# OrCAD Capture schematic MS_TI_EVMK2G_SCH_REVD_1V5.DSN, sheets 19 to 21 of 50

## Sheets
19 18. NAND FLASH & MICRO SD CARD: size C; title: NAND FLASH & SD CARD
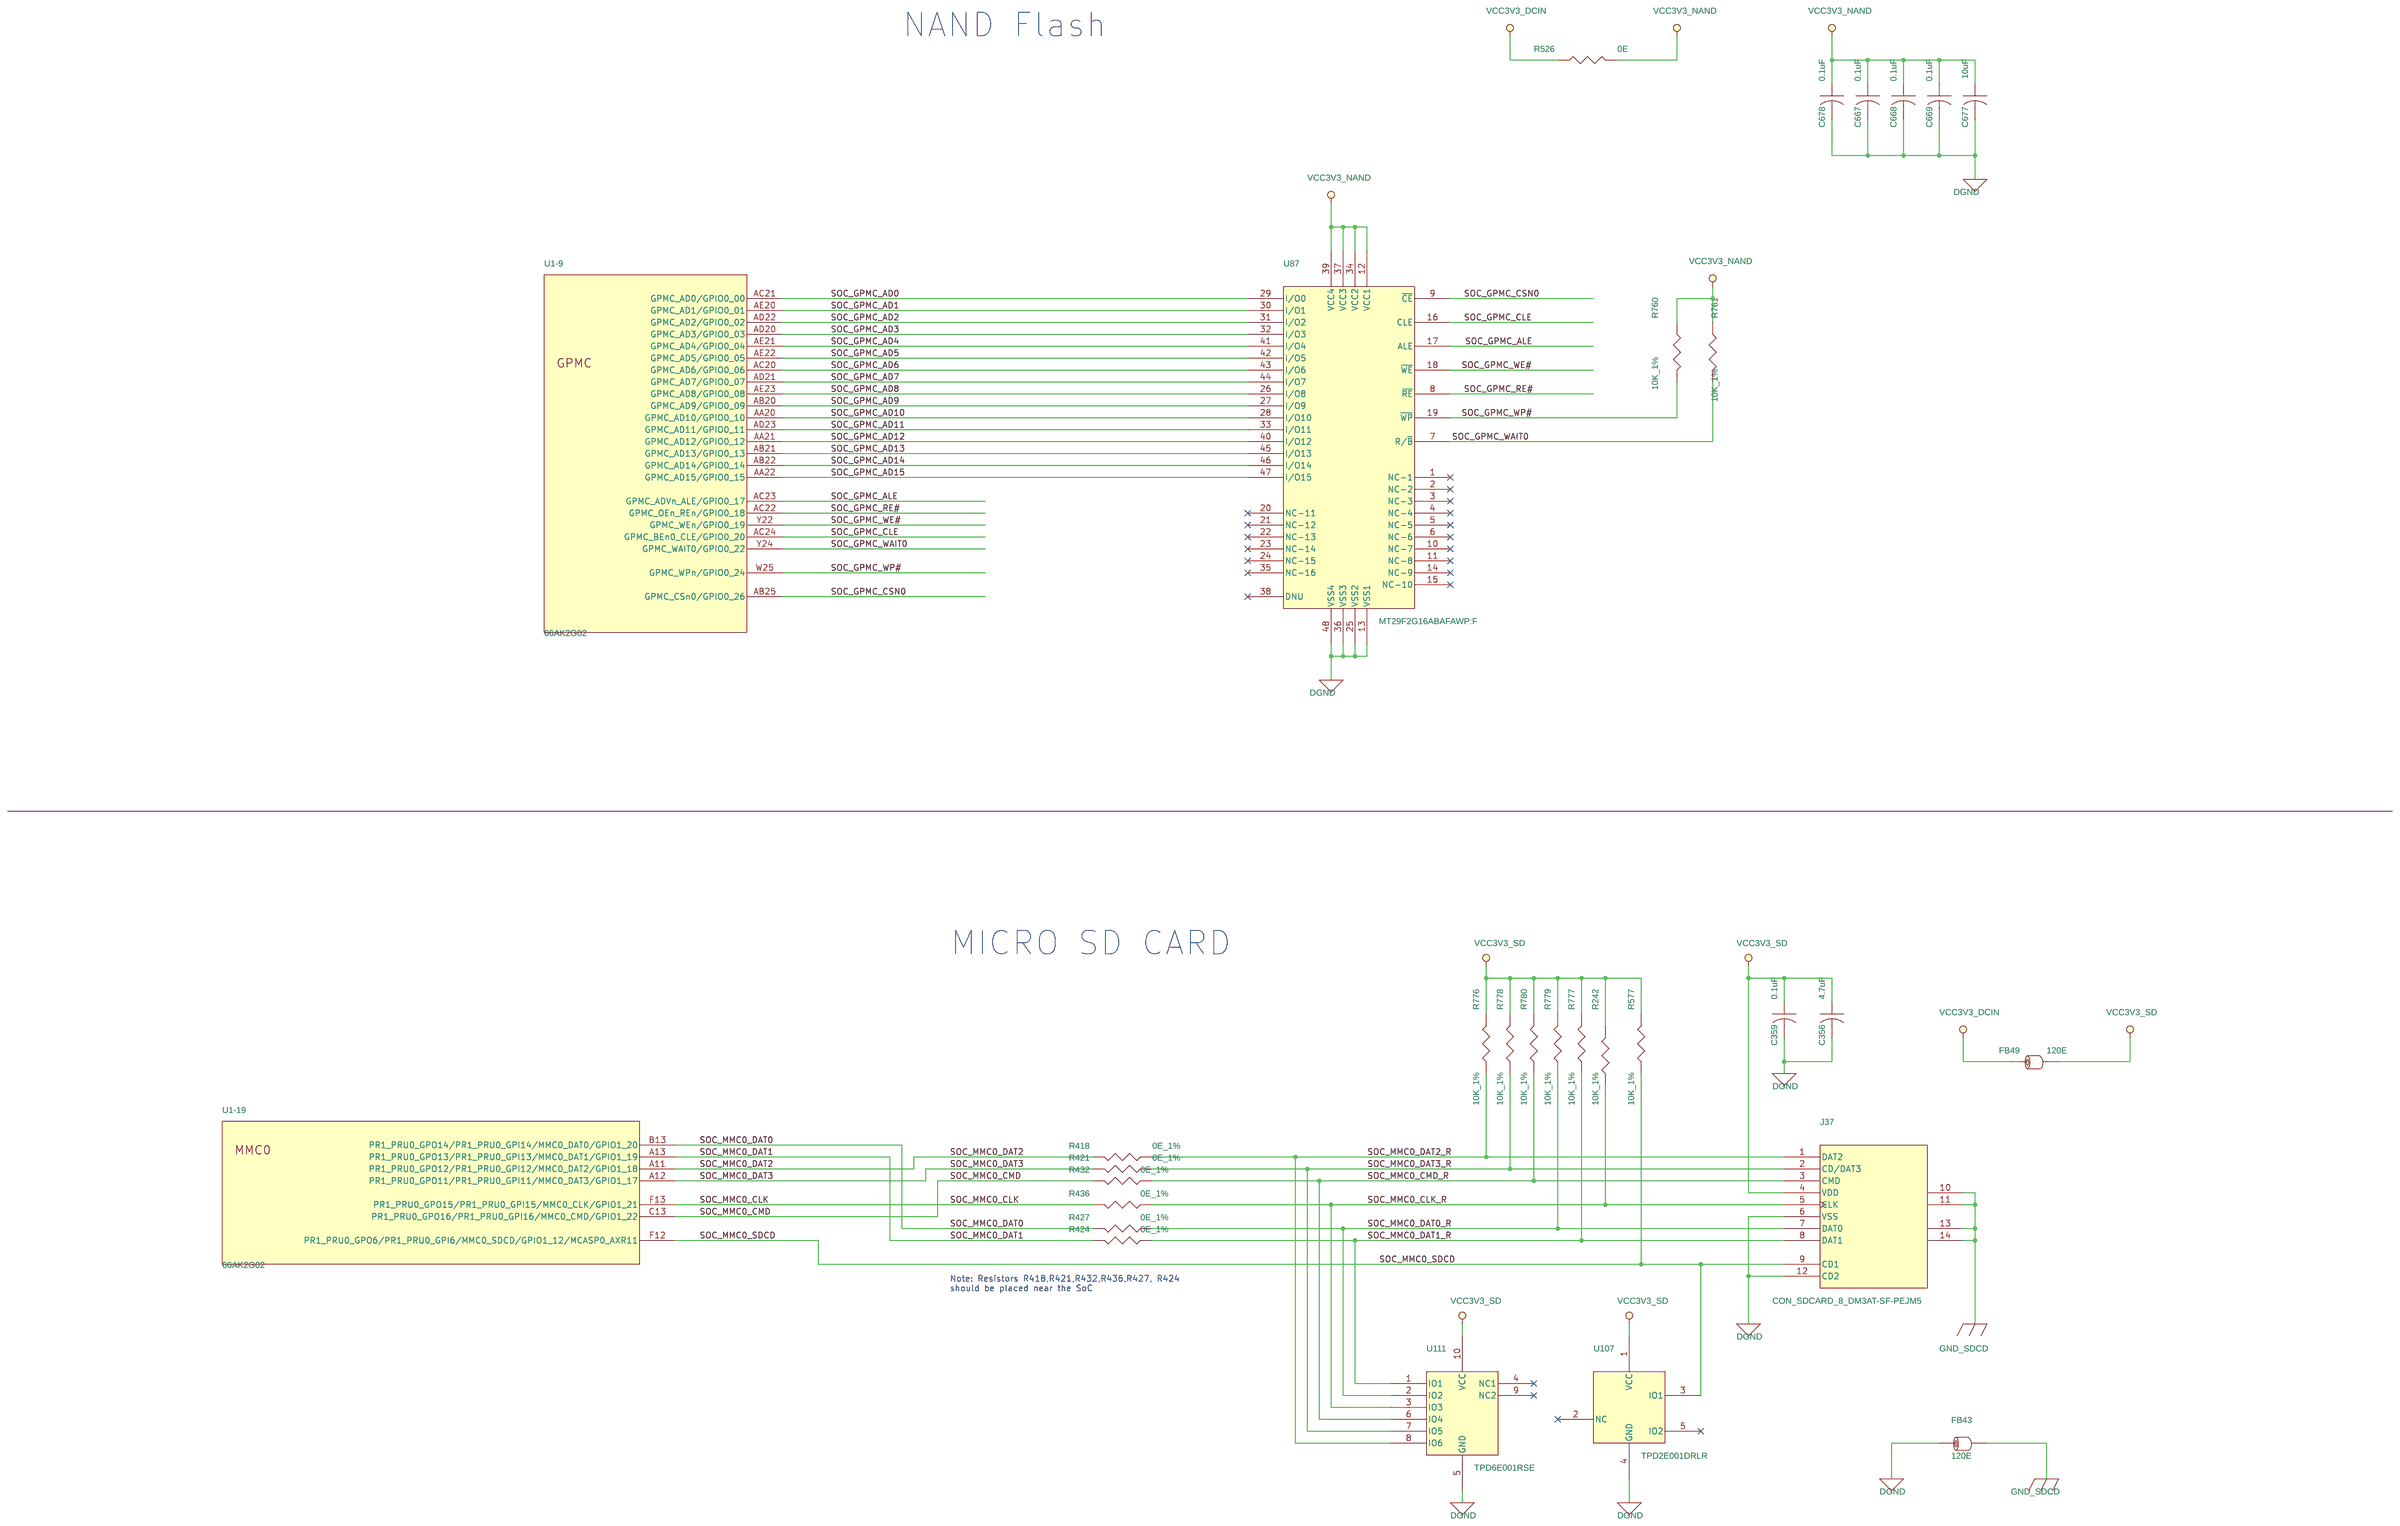
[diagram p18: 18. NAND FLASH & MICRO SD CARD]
20 19. DSS BUFFER: size C; title: DSS BUFFER SECTION
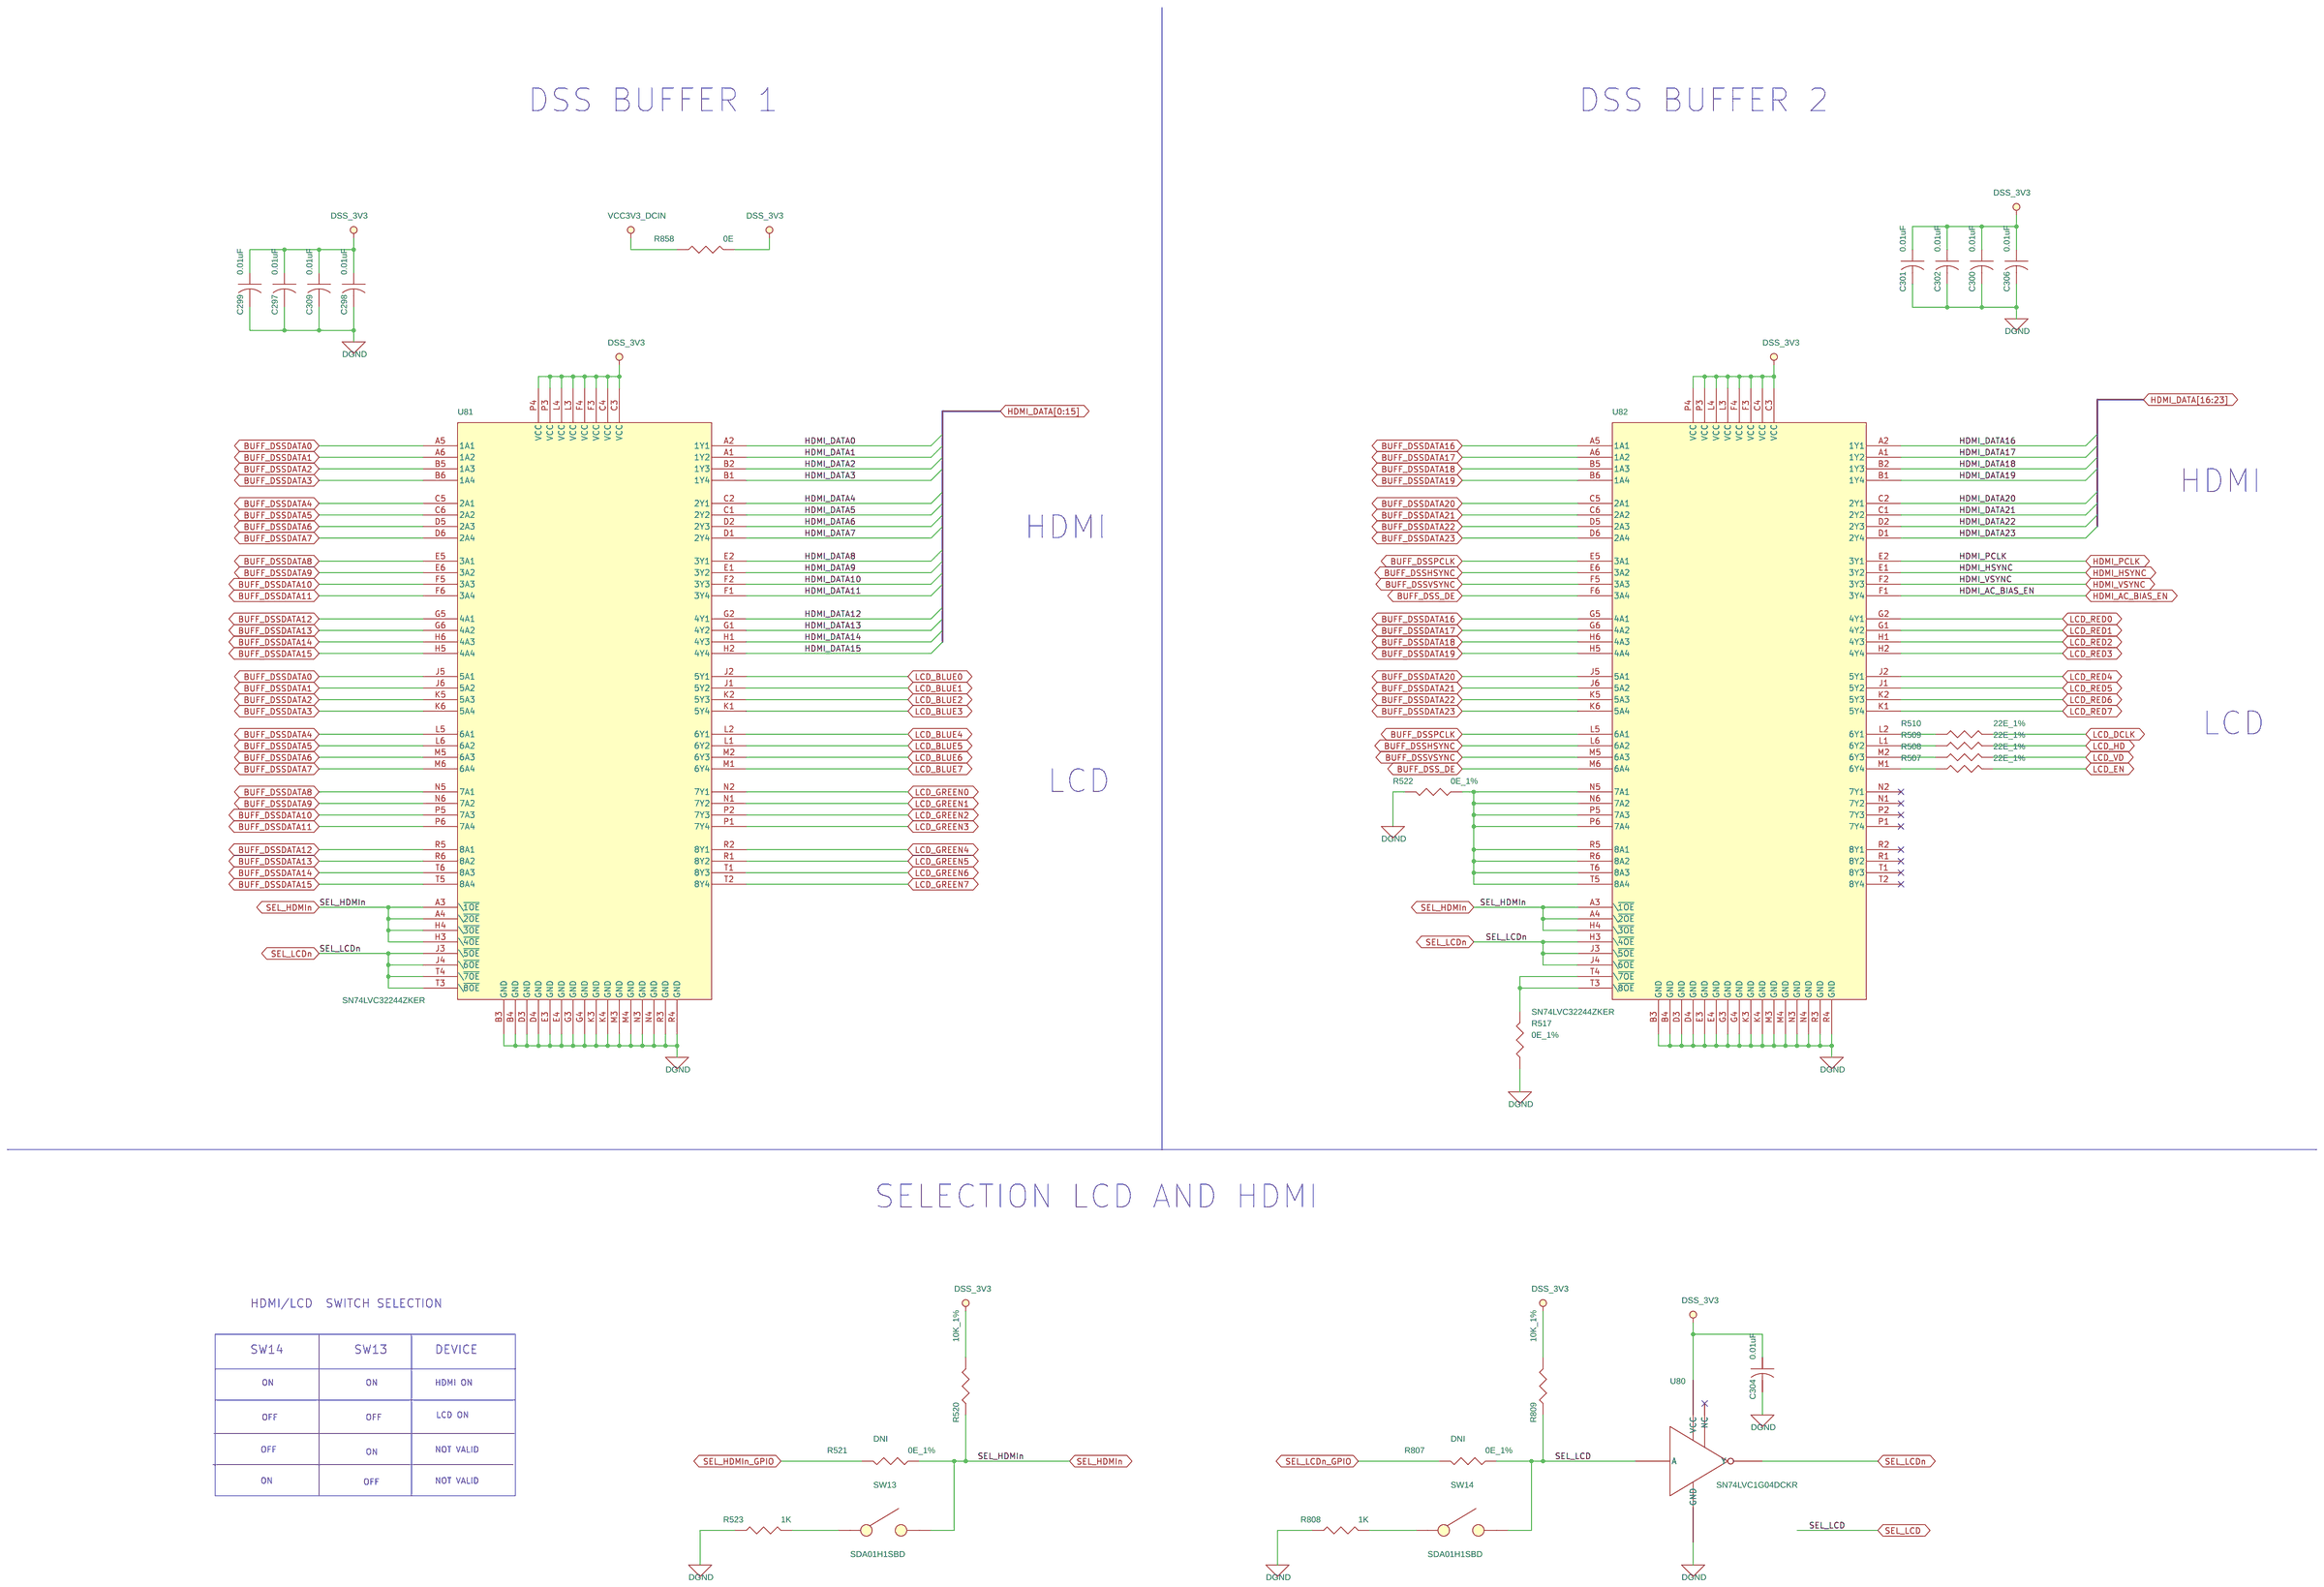
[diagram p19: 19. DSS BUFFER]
21 20. LCD & TOUCH CONNECTOR: size C; title: LCD & TOUCH SCREEN
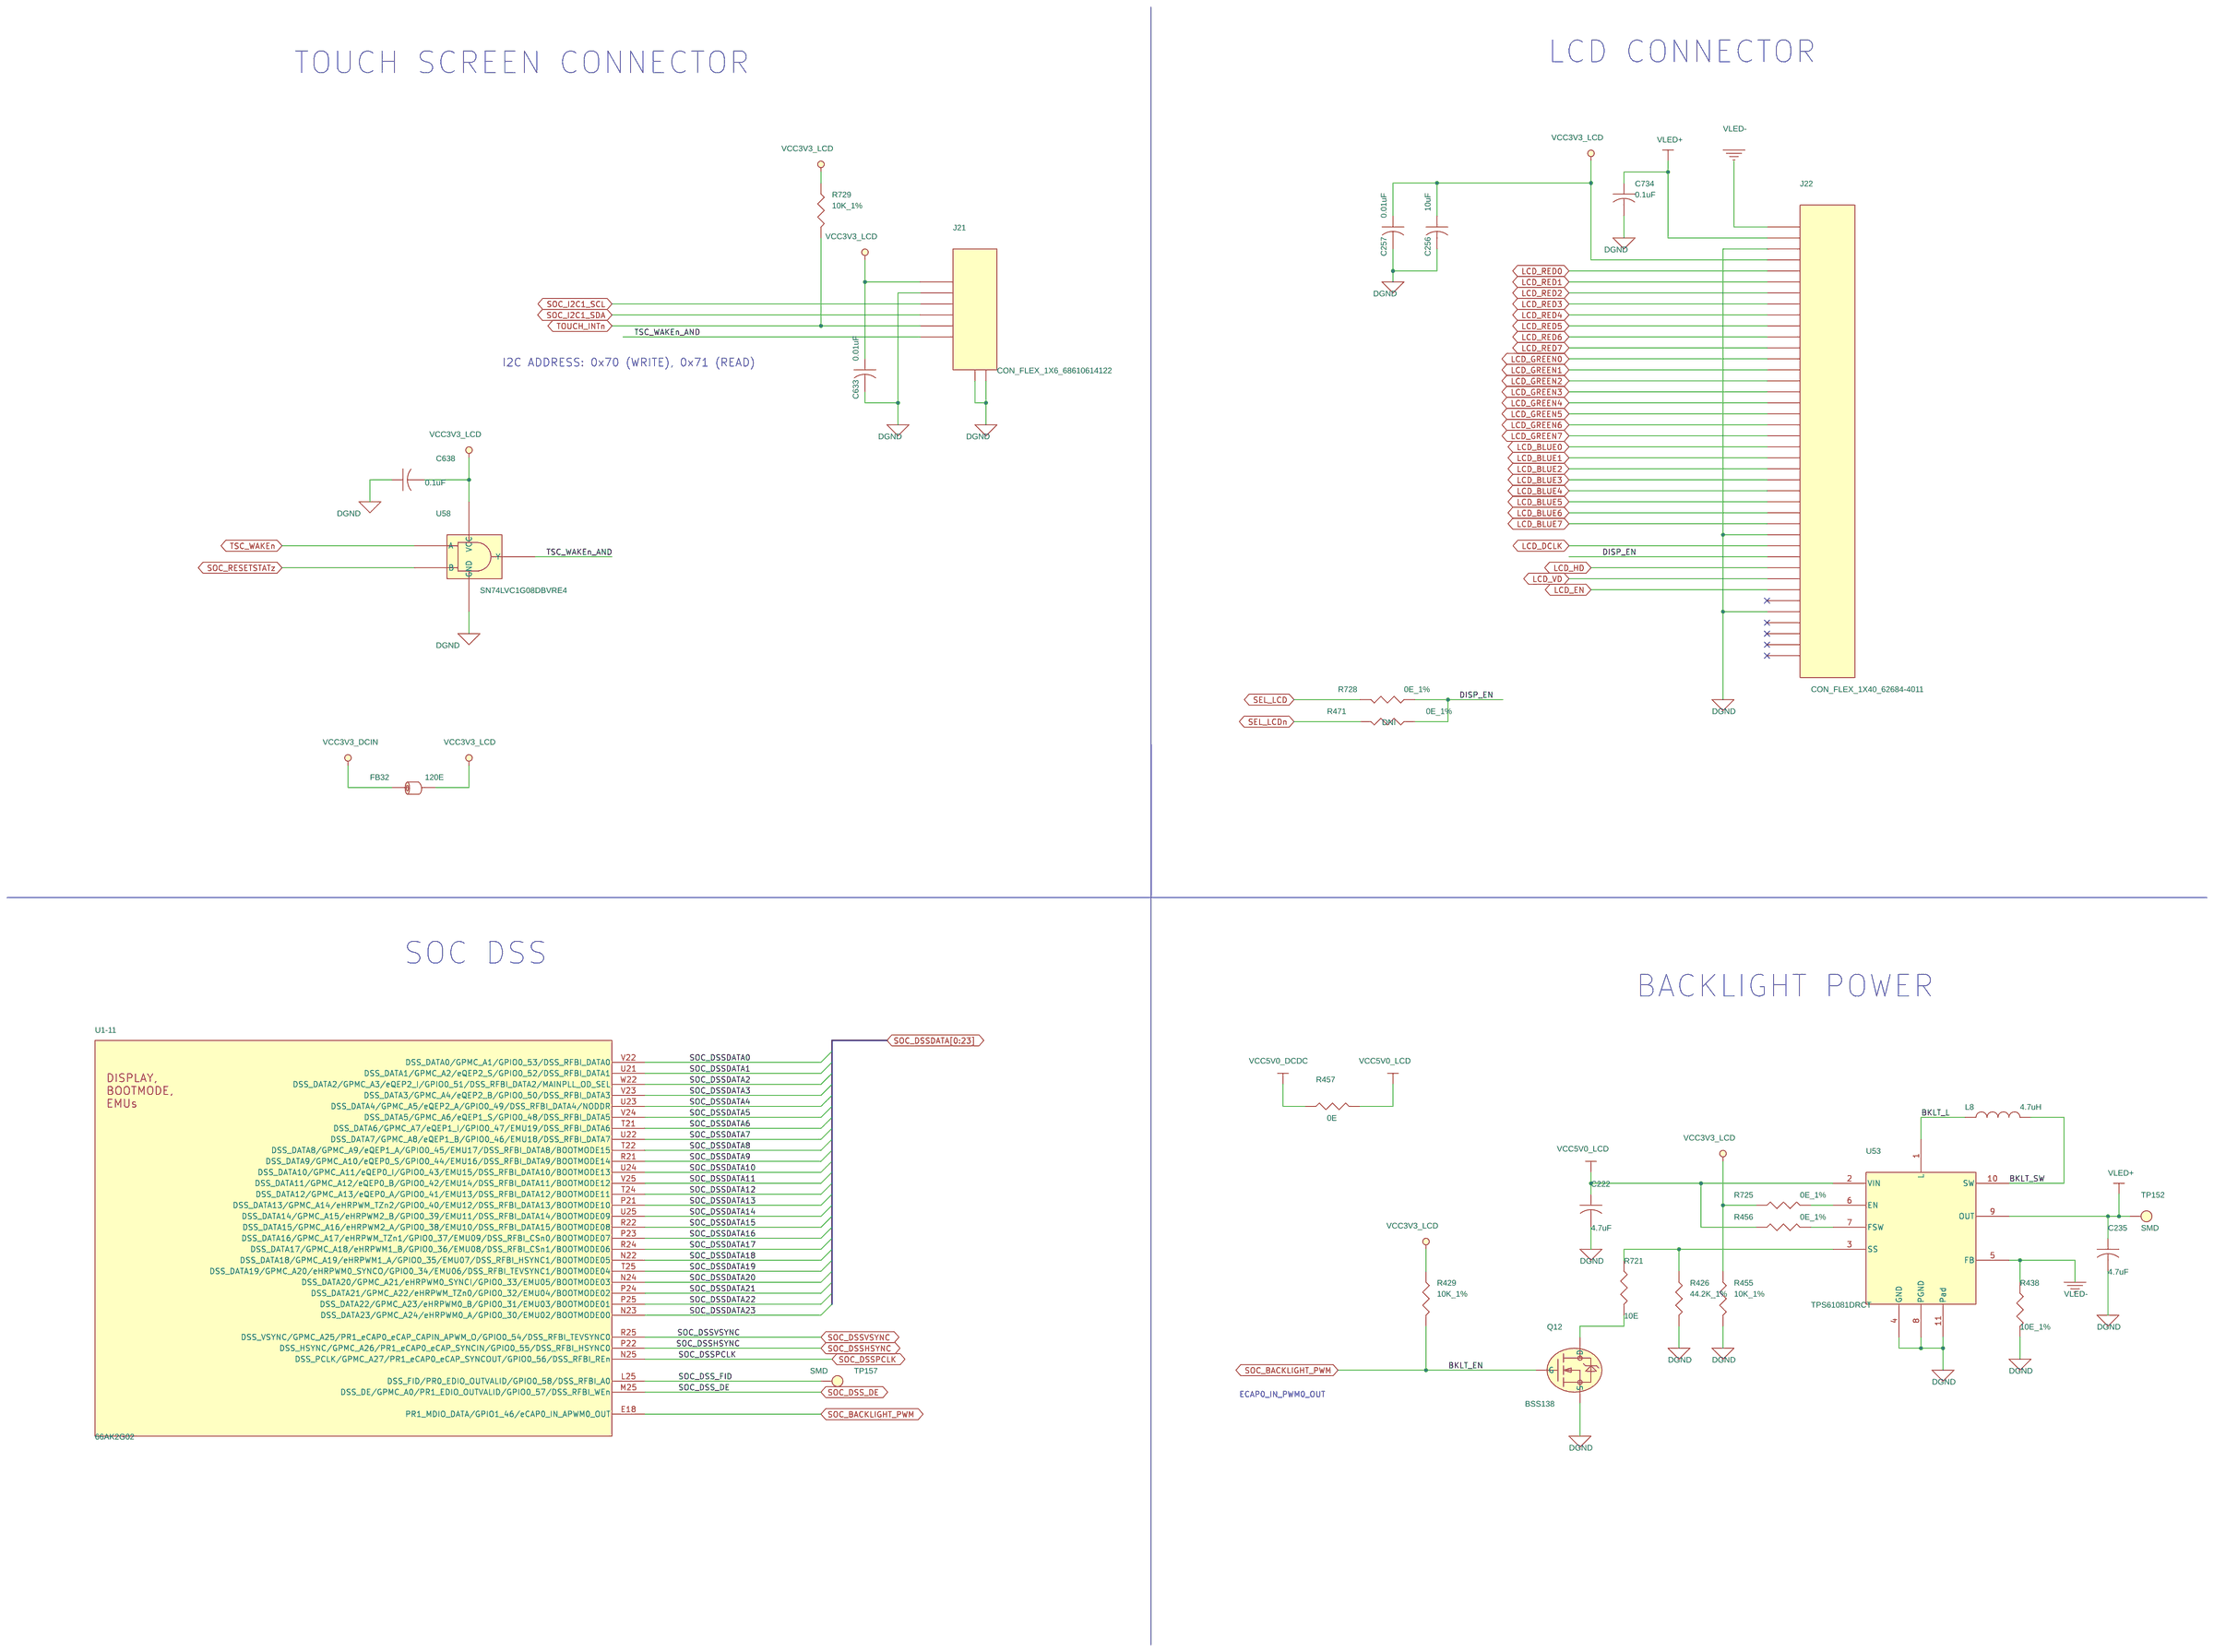
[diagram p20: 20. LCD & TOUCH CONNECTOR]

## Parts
sheet 18. NAND FLASH & MICRO SD CARD
C356  4.7uF  [CAP0603]
C359  0.1uF  [CAP0402]
C667  0.1uF  [CAP0402]
C668  0.1uF  [CAP0402]
C669  0.1uF  [CAP0402]
C677  10uF  [CAP0805]
C678  0.1uF  [CAP0402]
FB43  120E  [IND0402]
FB49  120E  [IND0402]
J37  CON_SDCARD_8_DM3AT-SF-PEJM5  [CON_SD_8_DM3AT-SF-PEJM_S_R_S]
R242  10K_1%  [RES0402]
R418  0E_1%  [RES0402]
R421  0E_1%  [RES0402]
R424  0E_1%  [RES0402]
R427  0E_1%  [RES0402]
R432  0E_1%  [RES0402]
R436  0E_1%  [RES0402]
R526  0E  [RES0402]
R577  10K_1%  [RES0402]
R760  10K_1%  [RES0402]
R761  10K_1%  [RES0402]
R776  10K_1%  [RES0402]
R777  10K_1%  [RES0402]
R778  10K_1%  [RES0402]
R779  10K_1%  [RES0402]
R780  10K_1%  [RES0402]
U87  MT29F2G16ABAFAWP:F  [TSOP48_19-68_730X480]
U107  TPD2E001DRLR  [SOT533-5]
U111  TPD6E001RSE  [UQFN10_19-68_80X60]
sheet 19. DSS BUFFER
C297  0.01uF  [CAP0402]
C298  0.01uF  [CAP0402]
C299  0.01uF  [CAP0402]
C300  0.01uF  [CAP0402]
C301  0.01uF  [CAP0402]
C302  0.01uF  [CAP0402]
C304  0.01uF  [CAP0402]
C306  0.01uF  [CAP0402]
C309  0.01uF  [CAP0402]
R507  22E_1%  [RES0402]
R508  22E_1%  [RES0402]
R509  22E_1%  [RES0402]
R510  22E_1%  [RES0402]
R517  0E_1%  [RES0402]
R520  10K_1%  [RES0402]
R521  0E_1%  [RES0402]
R522  0E_1%  [RES0402]
R523  1K  [RES0402]
R807  0E_1%  [RES0402]
R808  1K  [RES0402]
R809  10K_1%  [RES0402]
R858  0E  [RES0402]
SW13  SDA01H1SBD  [SW2_100X324-80_180X300_SMD]
SW14  SDA01H1SBD  [SW2_100X324-80_180X300_SMD]
U80  SN74LVC1G04DCKR  [SC70-5]
U81  SN74LVC32244ZKER  [LFBGA96_31-49_220X540]
U82  SN74LVC32244ZKER  [LFBGA96_31-49_220X540]
sheet 20. LCD & TOUCH CONNECTOR
C222  4.7uF  [CAP0603]
C235  4.7uF  [CAP0805]
C256  10uF  [CAP0805]
C257  0.01uF  [CAP0402]
C633  0.01uF  [CAP0402]
C638  0.1uF  [CAP0402]
C734  0.1uF  [CAP0402]
FB32  120E  [IND0402]
J21  CON_FLEX_1X6_68610614122  [CON_FLEX_6X1_68610_S_R_S]
J22  CON_FLEX_1X40_62684-4011  [CON_FLEX40X1_62684-40_S_R_S]
L8  4.7uH  [IND_VLCF5020T_205X210_SMD]
Q12  BSS138  [TO_SOT23-123]
R426  44.2K_1%  [RES0402]
R429  10K_1%  [RES0402]
R438  10E_1%  [RES0603]
R455  10K_1%  [RES0402]
R456  0E_1%  [RES0402]
R457  0E  [RES0402]
R471  0E_1%  [RES0402]
R721  10E  [RES0402]
R725  0E_1%  [RES0402]
R728  0E_1%  [RES0402]
R729  10K_1%  [RES0402]
TP152  SMD  [TP40_SMD]
TP157  SMD  [TP40_SMD]
U53  TPS61081DRCT  [SON10_19-68_130X130]
U58  SN74LVC1G08DBVRE4  [SOT23-5]
sheet 36. CLOCK DISTRIBUTION 2
U1  66AK2G02_BGA625  [BGASKT625_31-49_1270x1270]  (sections -1,-10,-11,-12,-13,-14,-15,-16,-17,-18,-19,-2,-20,-21,-22,-23,-24,-25,-26,-27,-28,-29,-3,-30,-31,-32,-33,-34,-35,-36,-37,-38,-4,-5,-6,-7,-8,-9)

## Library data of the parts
C222 C356 = CAP: CAP CERAMIC 4.7uF 16V 10% X5R 0603; Chkd/date: VASANTHA/230714; Crtd /date: BAVISH/060511; Custom_Duty: 15%; Customs_HS_Code: 85322990; Distributor_name: DIGIKEY; Distributor_part_number: 587-2786-1-ND; Height: 0.90MM; Mfr_name: TAIYO YUDEN; Mfr_part_number: EMK107ABJ475KA-T; Mistral Part No: 120011050004-R; Package: 0603; Part_type: CAPACITORS\CERAMIC; Project: HMC; RoHS: RoHS; Temperature: -55°C+85°C; Tolerance: 10%; Voltage: 16V; Wattage: NA; Weight: NA; Datasheet: Y:\MIS_DATABASE\DATASHEETS\CAPACITORS\EMK107.PDF
C359 C638 C667-C669 C678 = CAP: CAP CERAMIC 0.1uF 16V 10% X7R 0402; Alternate_mfr_name_A: KEMET; Alternate_mfr_part_number_A: C0402C104K4RACT; Chkd/date: MAZHAR/281108; Crtd /date: MAZHAR/030907; Custom_Duty: 15%; Customs_HS_Code: 85322990; Distributor_name: DIGIKEY; Distributor_name_A: DIGIKEY; Distributor_part_number: 490-3261-1-ND; Distributor_part_number_A: 399-3521-1-ND; Height: 0.55MM; Mfr_name: MURATA; Mfr_part_number: GRM155R71C104KA88D; Mistral Part No: 120009030060-R; Package: 0402; Part_type: CAPACITORS\CERAMIC; Project: SMART VIEW_IP CAMERA; Tolerance: 10%; Voltage: 16V; Datasheet: Y:\MIS_DATABASE\DATASHEETS\CAPACITORS\GRM188SERIES.PDF
C256 C677 = CAP: CAP CERAMIC 10uF 16V 10% X5R 0805; Alternate_mfr_name_A: TAIYO YUDEN; Alternate_mfr_part_number_A: EMK212BJ106KG-T; Chkd/date: RAVI/020511; Crtd /date: BAVISH/290411; Custom_Duty: 15%; Customs_HS_Code: 85322990; Distributor_name: DIGIKEY; Distributor_name_A: DIGIKEY; Distributor_part_number: 478-5165-1-ND; Distributor_part_number_A: 587-1295-1-ND; Height: 1.40MM; Mfr_name: AVX CORPORATION; Mfr_part_number: 0805YD106KAT2A; Mistral Part No: 120011040011-R; Package: 0805; Part_type: CAPACITORS\CERAMIC; Project: AOD_POD-RF; RoHS: RoHS; Temperature: -55°C+85°C; Tolerance: 10%; Voltage: 16V; Wattage: NA; Weight: NA; Datasheet: Y:\MIS_DATABASE\DATASHEETS\CAPACITORS\AVX_CERAMIC.PDF
FB32 FB43 FB49 = INDUCTOR_FERRITE: IND BEAD CHIP 120E 1.2A 0402; Chkd/date: ASHOK/240212; Crtd /date: BAVISH/060711; Custom_Duty: 24%; Customs_HS_Code: 85437099; Distributor_name: DIGIKEY; Distributor_part_number: 445-2981-1-ND; Height: 0.55MM; Mfr_name: TDK CORPORATION; Mfr_part_number: MPZ1005S121C; Mistral Part No: 130011070007-R; Package: 0402; Part_type: INDUCTOR; Project: SVDU; RoHS: RoHS; Temperature: -40°C+85°C; Tolerance: NA; Voltage: NA; Wattage: NA; Weight: 1mg; Datasheet: Y:\MIS_DATABASE\DATASHEETS\DISCRETES\INDUCTORS\MPZ1005.PDF
J37 = CON_SDCARD_8_DM3AT-SF-PEJM_0: CON SD CARD PUSH-PUSH 8POS SMD; Chkd/date: RAGESH/160511; Crtd /date: BAVISH/130511; Custom_Duty: 24%; Customs_HS_Code: 85369090; Distributor_name: DIGIKEY; Distributor_part_number: HR1964CT-ND; Height: 1.68MM; Mfr_name: HIROSE ELECTRIC EUROPE; Mfr_part_number: DM3AT-SF-PEJM5; Mistral Part No: 150011050017-R; Package: SMD; Part_type: CONNECTOR\MEMORY CARD; Project: HMC; RoHS: RoHS; Temperature: -25°C+85°C; Tolerance: NA; Voltage: NA; Wattage: NA; Weight: NA; Datasheet: Y:\MIS_DATABASE\DATASHEETS\CONNECTORS\DM3AT-PEJM.PDF
R242 R429 R455 R520 R577 R729 R760 R761 R776-R780 R809 = RESISTOR: RES 10K 1/16W 1% 0402; Alternate_mfr_name_A: AVX CORPORATION; Alternate_mfr_name_B: PANASONIC-ECG-ECG; Alternate_mfr_name_C: YAGEO AMERICA; Alternate_mfr_name_D: VISHAY; Alternate_mfr_part_number_A: CR05-103F-H; Alternate_mfr_part_number_B: ERJ-2RKF1002X; Alternate_mfr_part_number_C: 9C04021A1002FLHF3; Alternate_mfr_part_number_D: CRCW040210K0FKED; Chkd/date: SHREESHAIL/310506; Crtd /date: GEETHA/290506; Custom_Duty: 15%; Customs_HS_Code: 85332119; Distributor_name: DIGIKEY; Distributor_name_A: NA; Distributor_name_B: DIGIKEY; Distributor_name_C: DIGIKEY; Distributor_name_D: DIGIKEY; Distributor_part_number: 311-10.0KLRTR-ND; Distributor_part_number_A: NA; Distributor_part_number_B: P10.0KLCT-ND; Distributor_part_number_C: 311-10.0KLCT-ND; Distributor_part_number_D: 541-10.0KLCT-ND; Height: 0.40MM; Mfr_name: YAGEO AMERICA; Mfr_part_number: RC0402FR-0710KL; Mistral Part No: 110009030220-P; Package: 0402; Part_type: RESISTORS\FIXED; Project: VOCERA; RoHS: Pb-Free; Tolerance: 1%; Wattage: 1/16W; Datasheet: Y:\MIS_DATABASE\DATASHEETS\RESISTORS\YAGEO-RC0402.PDF
R418 R421 R424 R427 R432 R436 R456 R517 R522 R725 R728 = RESISTOR: RES 0E 1/16W 1% 0402; Chkd/date: MAZHAR/220709; Crtd /date: USMAN/270109; Custom_Duty: 15%; Customs_HS_Code: 85332119; Distributor_name: NA; Distributor_part_number: NA; Height: 0.40MM; Mfr_name: YAGEO AMERICA; Mfr_part_number: RC0402FR-070RL; Mistral Part No: 110009030085-P; Package: 0402; Part_type: RESISTORS\FIXED; Project: OMAP_EVM; RoHS: Pb-Free; Tolerance: 1%; Wattage: 1/16W; Datasheet: Y:\MIS_DATABASE\DATASHEETS\RESISTORS\CRCW0603.PDF
R457 R526 R858 = RESISTOR: RES 0E 1/10W 5% 0402; Chkd/date: NAVEED/241114; Crtd /date: NAVEED/201014; Custom_Duty: 15%; Customs_HS_Code: 85332119; Distributor_name: DIGIKEY; Distributor_part_number: P0.0JCT-ND; Height: 0.40MM; Mfr_name: PANASONIC-ECG; Mfr_part_number: ERJ-2GE0R00X; Mistral Part No: 110014100008-R; Package: 0402; Part_type: RESISTORS\FIXED; Project: AEGIS POM; RoHS: RoHS; Tolerance: 5%; Wattage: 1/10W; Datasheet: Y:\MIS_DATABASE\DATASHEETS\RESISTORS\ERJ12.PDF
U87 = MT29F2G16ABAEAWP_TSOP48: IC FLASH MEMORY 2-GBIT 16BIT 3.3V TSOP48; Chkd/date: USMAN/021214; Crtd /date: VASANTHA/071114; Custom_Duty: 15%; Customs_HS_Code: 85423100; Distributor_name: NA; Distributor_part_number: NA; Height: 1.20MM; Mfr_name: MICRON; Mistral Part No: 141114110001-R; Package: TSOP48; Part_type: ICS\DIGITAL\MEMORY; Project: GALILEO_EVM; RoHS: RoHS; Temperature: 0°C+70°C; Tolerance: NA; Voltage: 3.3V; Wattage: NA; Weight: NA; Datasheet: Y:\MIS_DATABASE\DATASHEETS\ICS\MEMORY\MT29F2G16ABAEAWP.PDF
U107 = TPD2E001DRLR_SOT-5: IC ESD-PROTECTION  ARRAY FOR HIGH_SPEED DATA INTERFACESSOT-5; Chkd/date: NAVEED/150714; Crtd /date: MUDDU/250510; Custom_Duty: 15%; Customs_HS_Code: 85423100; Distributor_name: DIGIKEY; Distributor_part_number: 296-21883-1-ND; Height: 0.60MM; Mfr_name: TEXAS INSTRUMENTS; Mistral Part No: 140110060007-R; Package: SOT-5; Part_type: ICS\ANALOG\ACTIVE FILTER; Project: CENTAURUS; RoHS: RoHS; Temperature: -40°C+85°C; Weight: NA; Datasheet: Y:\MIS_DATABASE\DATASHEETS\ICS\MISC\TPD2E001DRLR.PDF
U111 = TPD6E001RSE_UQFN10: IC 6CH ESD-PROTECTION ARRAY UQFN10; Chkd/date: USMAN/070612; Crtd /date: BAVISH/160811; Custom_Duty: 15%; Customs_HS_Code: 85423100; Distributor_name: DIGIKEY; Distributor_part_number: 296-21888-1-ND; Height: 0.60MM; Mfr_name: TEXAS INSTRUMENTS; Mistral Part No: 141011080020; Package: UQFN10; Part_type: ICS\INTERFACE; Project: DM385EVM_BASE-BOARD; RoHS: NA; Temperature: -40°C+85°C; Tolerance: NA; Voltage: NA; Wattage: NA; Weight: NA; Datasheet: Y:\MIS_DATABASE\DATASHEETS\ICS\INTERFACE\TPD6E001.PDF
C257 C297-C302 C304 C306 C309 C633 = CAP: CAP CERAMIC 0.01uF 16V 10% X7R 0402; Alternate_mfr_name_A: AVX CORPORATION; Alternate_mfr_name_B: KEMET; Alternate_mfr_name_D: TDK CORPORATION; Alternate_mfr_part_number_A: 0402YC103KAT2A; Alternate_mfr_part_number_B: C0402C103K4RACTU; Alternate_mfr_part_number_D: C1005X7R1C103K; Chkd/date: SHREESHAIL/180506; Crtd /date: MAZHAR/110506; Custom_Duty: 15%; Customs_HS_Code: 85322990; Distributor_name: DIGIKEY; Distributor_name_A: DIGIKEY; Distributor_name_B: DIGIKEY; Distributor_name_D: DIGIKEY; Distributor_part_number: PCC103BQCT-ND; Distributor_part_number_A: 478-1114-1-ND; Distributor_part_number_B: 399-1038-1-ND; Distributor_part_number_D: 445-1262-1-ND; Height: 0.55MM; Mfr_name: PANASONIC-ECG; Mfr_part_number: ECJ-0EB1C103K; Mistral Part No: 120009030032-R; Package: 0402; Part_type: CAPACITORS\CERAMIC; Project: VOCERA; RoHS: RoHS; Tolerance: 10%; Voltage: 16V; Datasheet: Y:\MIS_DATABASE\DATASHEETS\CAPACITORS\PAN-ECJ.PDF
R507-R510 = RESISTOR: RES 22E 1/16W 1% 0402; Alternate_mfr_name_A: VISHAY; Alternate_mfr_part_number_A: CRCW040222R0FKED; Chkd/date: SUHAS/290910; Crtd /date: MAZHAR/090909; Custom_Duty: 15%; Customs_HS_Code: 85332119; Distributor_name: DIGIKEY; Distributor_name_A: DIGIKEY; Distributor_part_number: 311-22.0LRCT-ND; Distributor_part_number_A: 541-22.0LCT-ND; Height: 0.40MM; Mfr_name: YAGEO AMERICA; Mfr_part_number: RC0402FR-0722RL; Mistral Part No: 110009090004-P; Package: 0402; Part_type: RESISTORS\FIXED; Project: VMEFMCD; Remarks: In alternate datasheet it is RoHS COMPLIANT. Y:\MIS_DATABASE\DATASHEETS\RESISTORS\CRCW0402.PDF; RoHS: Pb-Free; Temperature: -55°C+155°C; Tolerance: 1%; Voltage: 50V; Wattage: 1/16W; Weight: 0.8g/1000pcs; Datasheet: Y:\MIS_DATABASE\DATASHEETS\RESISTORS\YAGEO-RC0402.PDF
R471 R521 R807 = RESISTOR: RES 0E 1/16W 1% 0402; Chkd/date: MAZHAR/220709; Crtd /date: USMAN/270109; Custom_Duty: 15%; Customs_HS_Code: 85332119; Distributor_name: NA; Distributor_part_number: NA; Height: 0.40MM; Loading: DNI; Mfr_name: YAGEO AMERICA; Mfr_part_number: RC0402FR-070RL; Mistral Part No: 110009030085-P; Package: 0402; Part_type: RESISTORS\FIXED; Project: OMAP_EVM; RoHS: Pb-Free; Tolerance: 1%; Wattage: 1/16W; Datasheet: Y:\MIS_DATABASE\DATASHEETS\RESISTORS\CRCW0603.PDF
R523 R808 = RESISTOR: RES 1K 1/16W 5% 0402; Alternate_mfr_name_A: AVX CORPORATION; Alternate_mfr_name_C: YAGEO AMERICA; Alternate_mfr_part_number_A: CR05-102J-H; Alternate_mfr_part_number_C: RC0402JR-071KL; Chkd/date: SHREESHAIL/121205; Crtd /date: MAZHAR/230805; Custom_Duty: 15%; Customs_HS_Code: 85332119; Distributor_name: DIGIKEY; Distributor_name_A: NA; Distributor_name_C: DIGIKEY; Distributor_part_number: P1.0KJCT-ND; Distributor_part_number_A: NA; Distributor_part_number_C: 311-1.0KJRCT-ND; Height: 0.40MM; Mfr_name: PANASONIC-ECG; Mfr_part_number: ERJ-2GEJ102X; Mistral Part No: 110009030400-R; Package: 0402; Part_type: RESISTORS\FIXED; Project: HSE; RoHS: RoHS; Tolerance: 5%; Wattage: 1/16W; Datasheet: Y:\MIS_DATABASE\DATASHEETS\RESISTORS\ERJ12.PDF
SW13 SW14 = SW2: SWITCH DIP SPST LOW PROFILE SMD; Chkd/date: SARANYA/110314; Crtd /date: JAGADISH/280214; Custom_Duty: 24%; Customs_HS_Code: 85369090; Distributor_name: DIGIKEY; Distributor_part_number: CKN10358-ND; Height: 4.45MM; Mfr_name: C&K COMPONENTS; Mistral Part No: 130014030014-R; Package: SMD; Part_type: ELECTRO-MECHANICAL\SWITCH; Project: DMP; RoHS: RoHS; Temperature: -40°C+85°C; Tolerance: NA; Voltage: NA; Wattage: NA; Weight: NA; Datasheet: Y:\MIS_DATABASE\DATASHEETS\MISC\SWITCHES\SDAXXX_SERIES.PDF
U80 = SN74LVC1G04DCKR_SC70-5: IC SINGLE INVERTER GATE SC70-5; Chkd/date: SUHAS/221010; Crtd /date: USMAN/150709; Custom_Duty: 15%; Customs_HS_Code: 85423100; Distributor_name: DIGIKEY; Distributor_part_number: 296-11600-1-ND; Height: 1.10MM; Mfr_name: TEXAS INSTRUMENTS; Mistral Part No: 141009070007-R; Part_type: ICS\DIGITAL\GATES; Project: BUG_BASE-II; RoHS: Sb/ Br FREE; Temperature: -40°C+85°C; Datasheet: Y:\MIS_DATABASE\DATASHEETS\ICS\DIGITAL\GATES\SN74LVC1G04-1.PDF
U81 U82 = SN74LVC32244Z_LFBGA96: IC 32-BIT BUFFER DRIVER WITH 3-STATE OUTPUTS LFBGA96; Chkd/date: VASANTHA/150714; Crtd /date: BALACHANDAR/120614; Custom_Duty: 15%; Customs_HS_Code: 85423100; Distributor_name: DIGIKEY; Distributor_part_number: 296-23352-1-ND; Height: 1.40MM; Mfr_name: TEXAS INSTRUMENTS; Mistral Part No: 141014060009-R; Package: LFBGA96; Part_type: ICS\DIGITAL\COMBINATIONAL; Project: AEGIS; RoHS: RoHS; Temperature: -40°C+85°C; Tolerance: NA; Voltage: NA; Wattage: NA; Weight: NA; Datasheet: Y:\MIS_DATABASE\DATASHEETS\ICS\DIGITAL\COMBINATIONAL\SN74LVC32244.PDF
C235 = CAP: CAP CERAMIC 4.7uF 50V 20% X5R 0805; Chkd/date: VASANTHA/200614; Crtd /date: NAVEED/180614; Custom_Duty: 15%; Customs_HS_Code: 85322990; Distributor_name: DIGIKEY; Distributor_part_number: 445-5981-1-ND; Height: 1.45MM; Mfr_name: TDK CORPORATION; Mfr_part_number: C2012X5R1H475M; Mistral Part No: 120014060013-R; Package: 0805; Part_type: CAPACITORS\CERAMIC; Project: AEGIS_POM; RoHS: RoHS; Temperature: -55°C+85°C; Tolerance: 20%; Voltage: 50V; Wattage: NA; Weight: NA; Datasheet: Y:\MIS_DATABASE\DATASHEETS\CAPACITORS\C2012X5R.PDF
C734 = CAP: CAP CERAMIC 0.1uF 50V 10% X7R 0402; Alternate_mfr_name_A: TDK CORPORATION; Alternate_mfr_part_number_A: CGA2B3X7R1H104K; Chkd/date: BAVISH/081111; Crtd /date: CHAITHANYA/051011; Custom_Duty: 15%; Customs_HS_Code: 85322990; Distributor_name: DIGIKEY; Distributor_name_A: DIGIKEY; Distributor_part_number: 445-5932-1-ND; Distributor_part_number_A: 445-6899-1-ND; Height: 0.55MM; Mfr_name: TDK CORPORATION; Mfr_part_number: C1005X7R1H104K; Mistral Part No: 120011100014-R; Package: 0402; Part_type: CAPACITORS\CERAMIC; Project: VP-4000-BASE-BOARD; RoHS: RoHS; Temperature: -55°C+125°C; Tolerance: 10%; Voltage: 50V; Wattage: NA; Weight: NA; Datasheet: Y:\MIS_DATABASE\DATASHEETS\CAPACITORS\C1005X7.PDF
J21 = CON_FLEX_6X1_FF18: CON FPC 1X6 1MM PITCH RT SMD; Chkd/date: NAVEED/060115; Crtd /date: JEBRAN/211114; Custom_Duty: 24%; Customs_HS_Code: 85369090; Distributor_name: DIGIKEY; Distributor_part_number: 732-2002-1-ND; Height: 2.95MM; Mfr_name: WURTH ELECTRONICS INC; Mfr_part_number: 68610614122; Mistral Part No: 150014110009-R; Package: SMD; Part_type: CONNECTOR\FPC; Project: GALILEO EVM; RoHS: RoHS; Temperature: -25°C +85°C; Tolerance: NA; Voltage: NA; Wattage: NA; Weight: NA; Datasheet: Y:\MIS_DATABASE\DATASHEETS\CONNECTORS\6861-SERIES.PDF
J22 = CON_FLEX_40X1_62684-4021: CON FPC 1X40 0.50MM PITCH BTM RT SMD; Chkd/date: NAVEED/060115; Crtd /date: JEBRAN/211114; Custom_Duty: 24%; Customs_HS_Code: 85369090; Distributor_name: DIGIKEY; Distributor_part_number: 609-1195-1-ND; Height: 2.00MM; Mfr_name: FCI; Mfr_part_number: 62684-401100ALF; Mistral Part No: 150014110011-R; Package: SMD; Part_type: CONNECTOR\FPC; Project: GALILEO EVM; RoHS: RoHS; Temperature: NA; Tolerance: NA; Voltage: NA; Wattage: NA; Weight: NA; Datasheet: Y:\MIS_DATABASE\DATASHEETS\CONNECTORS\62684-SERIES.PDF
L8 = INDUCTOR: IND POWER 4.7uH 1.7A 30% SMD; Chkd/date: VASANTHA/230714; Crtd /date: BAVISH/120511; Custom_Duty: 24%; Customs_HS_Code: 85437099; Distributor_name: DIGIKEY; Distributor_part_number: 445-3207-1-ND; Height: 2.00MM; Mfr_name: TDK CORPORATION; Mfr_part_number: VLCF5020T-4R7N1R7-1; Mistral Part No: 130011050012-R; Package: SMD; Project: CENTAURUS_LCD-ADAPTER; RoHS: RoHS; Temperature: -40°C+105°C; Tolerance: 30%; Voltage: NA; Wattage: NA; Weight: NA; Datasheet: Y:\MIS_DATABASE\DATASHEETS\DISCRETES\INDUCTORS\VLCF5020T.PDF
Q12 = MOSFET_BSS138: IC MOSFET N-CHANNEL 50V 200mA SOT23-3; Chkd/date: SUHAS/191010; Crtd /date: USMAN/240709; Custom_Duty: 15%; Customs_HS_Code: 85423100; Distributor_name: DIGIKEY; Distributor_part_number: BSS138CT-ND; Height: 1.20MM; Mfr_name: DIODES INC; Mfr_part_number: BSS138-7-F; Mistral Part No: 142009070019-R; Package: SOT23-3; Part_type: ICS\POWER\MOSFET; Project: KHAN_MAIN; RoHS: RoHS; Temperature: -55°C+150°C; Voltage: 50V; Wattage: 300mW; Weight: 0.008g; Datasheet: Y:\MIS_DATABASE\DATASHEETS\DISCRETES\TRANSISTORS_FETS\BSS138.PDF
R426 = RESISTOR: RES 44.2K 1/16W 1% 0402; Alternate_mfr_name_A: YAGEO AMERICA; Alternate_mfr_name_B: VISHAY; Alternate_mfr_part_number_A: RC0402FR-0744K2L; Alternate_mfr_part_number_B: CRCW040244K2FKED; Chkd/date: MAZHAR/041208; Crtd /date: USMAN/181108; Custom_Duty: 15%; Customs_HS_Code: 85332119; Distributor_name: DIGIKEY; Distributor_name_A: MOUSER; Distributor_name_B: DIGIKEY; Distributor_part_number: P44.2KLCT-ND; Distributor_part_number_A: 603-RC0402FR-0744K2L; Distributor_part_number_B: 541-44.2KLCT-ND; Height: 0.40MM; Mfr_name: PANASONIC-ECG; Mfr_part_number: ERJ-2RKF4422X; Mistral Part No: 110009030845-R; Package: 0402; Part_type: RESISTORS\FIXED; Project: PICO PROJECTOR; RoHS: RoHS; Tolerance: 1%; Wattage: 1/16W; Datasheet: Y:\MIS_DATABASE\DATASHEETS\RESISTORS\PAN-ERJSERIES.PDF
R438 = RESISTOR: RES 10E 0.25W 1% 0603; Chkd/date: SUHAS/230910; Crtd /date: MUDDU/210610; Custom_Duty: 15%; Customs_HS_Code: 85332119; Distributor_name: DIGIKEY; Distributor_part_number: 541-10.0SCT-ND; Height: 0.50MM; Mfr_name: VISHAY; Mfr_part_number: CRCW060310R0FKEAHP; Mistral Part No: 110010060021-P; Package: 0603; Part_type: RESISTORS\FIXED; Project: NPOL_CONTROLLERCARD; RoHS: Pb-Free; Temperature: -55°C+125°C; Tolerance: 1%; Voltage: 50V; Wattage: 0.25W; Weight: 2g/1000pcs; Datasheet: Y:\MIS_DATABASE\DATASHEETS\RESISTORS\CRCW.PDF
R721 = RESISTOR: RES 10E 1/16W 5% 0402; Alternate_mfr_name_A: VISHAY; Alternate_mfr_name_B: PANASONIC-ECG-ECG; Alternate_mfr_name_C: YAGEO AMERICA; Alternate_mfr_part_number_A: CRCW040210R0JNED; Alternate_mfr_part_number_B: ERJ-2GEJ100X; Alternate_mfr_part_number_C: RC0402JR-0710RL; Chkd/date: SHREESHAIL/121205; Crtd /date: MAZHAR/120505; Custom_Duty: 15%; Customs_HS_Code: 85332119; Distributor_name: DIGIKEY; Distributor_name_A: DIGIKEY; Distributor_name_B: DIGIKEY; Distributor_name_C: DIGIKEY; Distributor_part_number: 311-10JCT-ND; Distributor_part_number_A: 541-10JCT-ND; Distributor_part_number_B: P10JTR-ND; Distributor_part_number_C: 311-10JRCT-ND; Height: 0.40MM; Mfr_name: YAGEO AMERICA; Mfr_part_number: 9C04021A10R0JLHF3; Mistral Part No: 110009030193; Package: 0402; Part_type: RESISTORS\FIXED; Project: G4_SVGA; Tolerance: 5%; Wattage: 1/16W; Datasheet: Y:\MIS_DATABASE\DATASHEETS\RESISTORS\YAGEO_RES.PDF
TP152 TP157 = TESTPOINT: TESTPOINT 40 SMD; Chkd/date: MAZHAR/190505; Crtd /date: MAZHAR/190505; Distributor_name: NA; Distributor_part_number: NA; Height: NA; Mfr_name: LOCAL; Mistral Part No: 130009030933; Part_type: MISC\TESTPOINT; Project: RAINIER-3
U53 = TPS61081DRCT_SON10: IC STEP-UP 1.3A DC/DC CONVERTER SON10; Chkd/date: SUHAS/211010; Crtd /date: MAZHAR/121009; Custom_Duty: 15%; Customs_HS_Code: 85423100; Distributor_name: DIGIKEY; Distributor_part_number: 296-21556-1-ND; Height: 1.00MM; Mfr_name: TEXAS INSTRUMENTS; Mistral Part No: 142009100003; Package: SON10; Part_type: ICS\POWER\DC-DC CONVERTER; Project: GEACOM_PHRAZER; RoHS: Sb/ Br FREE; Temperature: -40°C+85°C; Datasheet: Y:\MIS_DATABASE\DATASHEETS\ICS\POWER\TPS61081.PDF
U58 = SN74LVC1G08DBVRE4_SOT23-5: IC SINGLE 2-INPUT POSITIVE AND GATE SOT23-5; Chkd/date: SUHAS/221010; Crtd /date: USMAN/151008; Custom_Duty: 15%; Customs_HS_Code: 85423100; Distributor_name: DIGIKEY; Distributor_part_number: SN74LVC1G08DBVRE4-ND; Height: 1.45MM; Mfr_name: TEXAS INSTRUMENTS; Mistral Part No: 141009060026-R; Part_type: ICS\DIGITAL\GATES; Project: KHAN_MAIN; RoHS: Sb/ Br FREE; Temperature: -40°C+85°C; Datasheet: Y:\MIS_DATABASE\DATASHEETS\ICS\DIGITAL\GATES\SN74LVC1G08.PDF
U1 = 66AK2G02_BGA625: IC ARM CORTEX AND DSP 32 BIT MICROPROCESSOR BGA625; Chkd/date: NAVEED/141114; Color: Default; Crtd /date: VASANTHA/081014; Custom_Duty: 15%; Customs_HS_Code: 85423100; Distributor_name: NA; Distributor_part_number: NA; Height: 1.70MM; Location X-Coordinate: 0; Location Y-Coordinate: 0; Mfr_name: TEXAS INSTRUMENTS; Mfr_part_number: 66AK2G02; Mistral Part No: 141014100003; Package: BGA625; Part_type: ICS\DIGITAL\MICROPROCESSOR; Power Pins Visible: False; Primitive: DEFAULT; Project: GALILEO_EVM; Tolerance: NA; Voltage: NA; Wattage: NA; Weight: NA; Datasheet: Y:\MIS_DATABASE\DATASHEETS\ICS\DIGITAL\MICROCONTROLLER\SG-BGA-6094.PDF    Y:\MIS_DATABASE\DATASHEETS\ICS\DIGITAL\MICROCONTROLLER\SG-BGA_FP.PDF

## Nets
DGND: C222.2 C235.2 C256.2 C257.2 C297.2 C298.2 C299.2 C300.2 C301.2 C302.2 C304.2 C306.2 C309.2 C356.2 C359.2 C633.2 C638.1 C667.2 C668.2 C669.2 C677.2 C678.2 C734.2 FB43.1 J21.2 J21.7 J21.8 J22.3 J22.29 J22.36 J37.6(VSS) J37.12(CD2) Q12.2(S) R426.2 R438.2 R455.2 R517.1 R522.2 R523.1 R808.1 U53.4(GND) U53.8(PGND) U53.11(Pad) U58.3(GND) U80.3(GND) U81.B3(GND) U81.B4(GND) U81.D3(GND) U81.D4(GND) U81.E3(GND) U81.E4(GND) U81.G3(GND) U81.G4(GND) U81.K3(GND) U81.K4(GND) U81.M3(GND) U81.M4(GND) U81.N3(GND) U81.N4(GND) U81.R3(GND) U81.R4(GND) U82.B3(GND) U82.B4(GND) U82.D3(GND) U82.D4(GND) U82.E3(GND) U82.E4(GND) U82.G3(GND) U82.G4(GND) U82.K3(GND) U82.K4(GND) U82.M3(GND) U82.M4(GND) U82.N3(GND) U82.N4(GND) U82.R3(GND) U82.R4(GND) U87.13(VSS1) U87.25(VSS2) U87.36(VSS3) U87.48(VSS4) U107.4(GND) U111.5(GND) ; also on sheet 1 11 12 13 14 15 16 17 18 22 23 24 25 26 27 28 29 30 31 32 33 34 35 36 37 38 39 40 41 42 43 44 45 46 47 48 49 50
GND_SDCD: FB43.2 J37.10 J37.11 J37.13 J37.14
VCC3V3_DCIN: FB32.1 FB49.1 R526.1 R858.1 ; also on sheet 11 17 18 22 23 24 25 26 27 28 29 30 31 32 33 34 35 36 37 38 43 44 45 46 47 48 50
VCC3V3_LCD: C256.1 C257.1 C633.1 C638.2 FB32.2 J21.1 J22.4 R429.1 R455.1 R725.1 R729.1 U58.5(VCC)
VCC3V3_NAND: C667.1 C668.1 C669.1 C677.1 C678.1 R526.2 R760.1 R761.1 U87.12(VCC1) U87.34(VCC2) U87.37(VCC3) U87.39(VCC4)
VCC3V3_SD: C356.1 C359.1 FB49.2 J37.4(VDD) R242.2 R577.2 R776.2 R777.2 R778.2 R779.2 R780.2 U107.1(VCC) U111.10(VCC)
VCC5V0_DCDC: R457.1 ; also on sheet 22 27 30 44 46 48 49 50
VCC5V0_LCD: C222.1 R456.1 R457.2 U53.2(VIN)
BKLT_L: L8.1 U53.1(L)
BKLT_SW: L8.2 U53.10(SW)
BUFF_DSS_DE: U82.F6(3A4) U82.M6(6A4) ; also on sheet 38
BUFF_DSSDATA0: U81.A5(1A1) U81.J5(5A1) ; also on sheet 38
BUFF_DSSDATA1: U81.A6(1A2) U81.J6(5A2) ; also on sheet 38
BUFF_DSSDATA2: U81.B5(1A3) U81.K5(5A3) ; also on sheet 38
BUFF_DSSDATA3: U81.B6(1A4) U81.K6(5A4) ; also on sheet 38
BUFF_DSSDATA4: U81.C5(2A1) U81.L5(6A1) ; also on sheet 38
BUFF_DSSDATA5: U81.C6(2A2) U81.L6(6A2) ; also on sheet 38
BUFF_DSSDATA6: U81.D5(2A3) U81.M5(6A3) ; also on sheet 38
BUFF_DSSDATA7: U81.D6(2A4) U81.M6(6A4) ; also on sheet 38
BUFF_DSSDATA8: U81.E5(3A1) U81.N5(7A1) ; also on sheet 38
BUFF_DSSDATA9: U81.E6(3A2) U81.N6(7A2) ; also on sheet 38
BUFF_DSSDATA10: U81.F5(3A3) U81.P5(7A3) ; also on sheet 38
BUFF_DSSDATA11: U81.F6(3A4) U81.P6(7A4) ; also on sheet 38
BUFF_DSSDATA12: U81.G5(4A1) U81.R5(8A1) ; also on sheet 38
BUFF_DSSDATA13: U81.G6(4A2) U81.R6(8A2) ; also on sheet 38
BUFF_DSSDATA14: U81.H6(4A3) U81.T6(8A3) ; also on sheet 38
BUFF_DSSDATA15: U81.H5(4A4) U81.T5(8A4) ; also on sheet 38
BUFF_DSSDATA16: U82.A5(1A1) U82.G5(4A1) ; also on sheet 38
BUFF_DSSDATA17: U82.A6(1A2) U82.G6(4A2) ; also on sheet 38
BUFF_DSSDATA18: U82.B5(1A3) U82.H6(4A3) ; also on sheet 38
BUFF_DSSDATA19: U82.B6(1A4) U82.H5(4A4) ; also on sheet 38
BUFF_DSSDATA20: U82.C5(2A1) U82.J5(5A1) ; also on sheet 38
BUFF_DSSDATA21: U82.C6(2A2) U82.J6(5A2) ; also on sheet 38
BUFF_DSSDATA22: U82.D5(2A3) U82.K5(5A3) ; also on sheet 38
BUFF_DSSDATA23: U82.D6(2A4) U82.K6(5A4) ; also on sheet 38
BUFF_DSSHSYNC: U82.E6(3A2) U82.L6(6A2) ; also on sheet 38
BUFF_DSSPCLK: U82.E5(3A1) U82.L5(6A1) ; also on sheet 38
BUFF_DSSVSYNC: U82.F5(3A3) U82.M5(6A3) ; also on sheet 38
DISP_EN: J22.31 R471.1 R728.2
DSS_3V3: C297.1 C298.1 C299.1 C300.1 C301.1 C302.1 C304.1 C306.1 C309.1 R520.2 R809.2 R858.2 U80.5(VCC) U81.C3(VCC) U81.C4(VCC) U81.F3(VCC) U81.F4(VCC) U81.L3(VCC) U81.L4(VCC) U81.P3(VCC) U81.P4(VCC) U82.C3(VCC) U82.C4(VCC) U82.F3(VCC) U82.F4(VCC) U82.L3(VCC) U82.L4(VCC) U82.P3(VCC) U82.P4(VCC)
HDMI_AC_BIAS_EN: U82.F1(3Y4) ; also on sheet 22
HDMI_DATA0: U81.A2(1Y1) ; also on sheet 22
HDMI_DATA1: U81.A1(1Y2) ; also on sheet 22
HDMI_DATA2: U81.B2(1Y3) ; also on sheet 22
HDMI_DATA3: U81.B1(1Y4) ; also on sheet 22
HDMI_DATA4: U81.C2(2Y1) ; also on sheet 22
HDMI_DATA5: U81.C1(2Y2) ; also on sheet 22
HDMI_DATA6: U81.D2(2Y3) ; also on sheet 22
HDMI_DATA7: U81.D1(2Y4) ; also on sheet 22
HDMI_DATA8: U81.E2(3Y1) ; also on sheet 22
HDMI_DATA9: U81.E1(3Y2) ; also on sheet 22
HDMI_DATA10: U81.F2(3Y3) ; also on sheet 22
HDMI_DATA11: U81.F1(3Y4) ; also on sheet 22
HDMI_DATA12: U81.G2(4Y1) ; also on sheet 22
HDMI_DATA13: U81.G1(4Y2) ; also on sheet 22
HDMI_DATA14: U81.H1(4Y3) ; also on sheet 22
HDMI_DATA15: U81.H2(4Y4) ; also on sheet 22
HDMI_DATA16: U82.A2(1Y1) ; also on sheet 22
HDMI_DATA17: U82.A1(1Y2) ; also on sheet 22
HDMI_DATA18: U82.B2(1Y3) ; also on sheet 22
HDMI_DATA19: U82.B1(1Y4) ; also on sheet 22
HDMI_DATA20: U82.C2(2Y1) ; also on sheet 22
HDMI_DATA21: U82.C1(2Y2) ; also on sheet 22
HDMI_DATA22: U82.D2(2Y3) ; also on sheet 22
HDMI_DATA23: U82.D1(2Y4) ; also on sheet 22
HDMI_HSYNC: U82.E1(3Y2) ; also on sheet 22
HDMI_PCLK: U82.E2(3Y1) ; also on sheet 22
HDMI_VSYNC: U82.F2(3Y3) ; also on sheet 22
LCD_BLUE0: J22.21 U81.J2(5Y1)
LCD_BLUE1: J22.22 U81.J1(5Y2)
LCD_BLUE2: J22.23 U81.K2(5Y3)
LCD_BLUE3: J22.24 U81.K1(5Y4)
LCD_BLUE4: J22.25 U81.L2(6Y1)
LCD_BLUE5: J22.26 U81.L1(6Y2)
LCD_BLUE6: J22.27 U81.M2(6Y3)
LCD_BLUE7: J22.28 U81.M1(6Y4)
LCD_DCLK: J22.30 R510.2
LCD_EN: J22.34 R507.2
LCD_GREEN0: J22.13 U81.N2(7Y1)
LCD_GREEN1: J22.14 U81.N1(7Y2)
LCD_GREEN2: J22.15 U81.P2(7Y3)
LCD_GREEN3: J22.16 U81.P1(7Y4)
LCD_GREEN4: J22.17 U81.R2(8Y1)
LCD_GREEN5: J22.18 U81.R1(8Y2)
LCD_GREEN6: J22.19 U81.T1(8Y3)
LCD_GREEN7: J22.20 U81.T2(8Y4)
LCD_HD: J22.32 R509.2
LCD_RED0: J22.5 U82.G2(4Y1)
LCD_RED1: J22.6 U82.G1(4Y2)
LCD_RED2: J22.7 U82.H1(4Y3)
LCD_RED3: J22.8 U82.H2(4Y4)
LCD_RED4: J22.9 U82.J2(5Y1)
LCD_RED5: J22.10 U82.J1(5Y2)
LCD_RED6: J22.11 U82.K2(5Y3)
LCD_RED7: J22.12 U82.K1(5Y4)
LCD_VD: J22.33 R508.2
SEL_HDMIn: R520.1 R521.1 SW13.2 U81.A3(\~{1OE}) U81.A4(\~{2OE}) U81.H3(\~{4OE}) U81.H4(\~{3OE}) U82.A3(\~{1OE}) U82.A4(\~{2OE}) U82.H4(\~{3OE}) ; also on sheet 35
SEL_HDMIn_GPIO: R521.2 ; also on sheet 12
SEL_LCD: R728.1 R807.1 R809.1 SW14.2 U80.2(A)
SEL_LCDn: R471.2 U80.4(Y) U81.J3(\~{5OE}) U81.J4(\~{6OE}) U81.T3(\~{8OE}) U81.T4(\~{7OE}) U82.H3(\~{4OE}) U82.J3(\~{5OE}) U82.J4(\~{6OE}) ; also on sheet 35
SEL_LCDn_GPIO: R807.2 ; also on sheet 12
SOC_BACKLIGHT_PWM: Q12.1(G) R429.2 U1.E18(PR1_MDIO_DATA/GPIO1_46/eCAP0_IN_APWM0_OUT)
SOC_DSS_DE: U1.M25(DSS_DE/GPMC_A0/PR1_EDIO_OUTVALID/GPIO0_57/DSS_RFBI_WEn) ; also on sheet 38
SOC_DSS_FID: TP157.1(TP) U1.L25(DSS_FID/PR0_EDIO_OUTVALID/GPIO0_58/DSS_RFBI_A0)
SOC_DSSDATA0: U1.V22(DSS_DATA0/GPMC_A1/GPIO0_53/DSS_RFBI_DATA0) ; also on sheet 38
SOC_DSSDATA1: U1.U21(DSS_DATA1/GPMC_A2/eQEP2_S/GPIO0_52/DSS_RFBI_DATA1) ; also on sheet 38
SOC_DSSDATA2: U1.W22(DSS_DATA2/GPMC_A3/eQEP2_I/GPIO0_51/DSS_RFBI_DATA2/MAINPLL_OD_SEL) ; also on sheet 38
SOC_DSSDATA3: U1.V23(DSS_DATA3/GPMC_A4/eQEP2_B/GPIO0_50/DSS_RFBI_DATA3) ; also on sheet 38
SOC_DSSDATA4: U1.U23(DSS_DATA4/GPMC_A5/eQEP2_A/GPIO0_49/DSS_RFBI_DATA4/NODDR) ; also on sheet 38
SOC_DSSDATA5: U1.V24(DSS_DATA5/GPMC_A6/eQEP1_S/GPIO0_48/DSS_RFBI_DATA5) ; also on sheet 38
SOC_DSSDATA6: U1.T21(DSS_DATA6/GPMC_A7/eQEP1_I/GPIO0_47/EMU19/DSS_RFBI_DATA6) ; also on sheet 38
SOC_DSSDATA7: U1.U22(DSS_DATA7/GPMC_A8/eQEP1_B/GPIO0_46/EMU18/DSS_RFBI_DATA7) ; also on sheet 38
SOC_DSSDATA8: U1.T22(DSS_DATA8/GPMC_A9/eQEP1_A/GPIO0_45/EMU17/DSS_RFBI_DATA8/BOOTMODE15) ; also on sheet 38
SOC_DSSDATA9: U1.R21(DSS_DATA9/GPMC_A10/eQEP0_S/GPIO0_44/EMU16/DSS_RFBI_DATA9/BOOTMODE14) ; also on sheet 38
SOC_DSSDATA10: U1.U24(DSS_DATA10/GPMC_A11/eQEP0_I/GPIO0_43/EMU15/DSS_RFBI_DATA10/BOOTMODE13) ; also on sheet 38
SOC_DSSDATA11: U1.V25(DSS_DATA11/GPMC_A12/eQEP0_B/GPIO0_42/EMU14/DSS_RFBI_DATA11/BOOTMODE12) ; also on sheet 38
SOC_DSSDATA12: U1.T24(DSS_DATA12/GPMC_A13/eQEP0_A/GPIO0_41/EMU13/DSS_RFBI_DATA12/BOOTMODE11) ; also on sheet 38
SOC_DSSDATA13: U1.P21(DSS_DATA13/GPMC_A14/eHRPWM_TZn2/GPIO0_40/EMU12/DSS_RFBI_DATA13/BOOTMODE10) ; also on sheet 38
SOC_DSSDATA14: U1.U25(DSS_DATA14/GPMC_A15/eHRPWM2_B/GPIO0_39/EMU11/DSS_RFBI_DATA14/BOOTMODE09) ; also on sheet 38
SOC_DSSDATA15: U1.R22(DSS_DATA15/GPMC_A16/eHRPWM2_A/GPIO0_38/EMU10/DSS_RFBI_DATA15/BOOTMODE08) ; also on sheet 38
SOC_DSSDATA16: U1.P23(DSS_DATA16/GPMC_A17/eHRPWM_TZn1/GPIO0_37/EMU09/DSS_RFBI_CSn0/BOOTMODE07) ; also on sheet 38
SOC_DSSDATA17: U1.R24(DSS_DATA17/GPMC_A18/eHRPWM1_B/GPIO0_36/EMU08/DSS_RFBI_CSn1/BOOTMODE06) ; also on sheet 38
SOC_DSSDATA18: U1.N22(DSS_DATA18/GPMC_A19/eHRPWM1_A/GPIO0_35/EMU07/DSS_RFBI_HSYNC1/BOOTMODE05) ; also on sheet 38
SOC_DSSDATA19: U1.T25(DSS_DATA19/GPMC_A20/eHRPWM0_SYNCO/GPIO0_34/EMU06/DSS_RFBI_TEVSYNC1/BOOTMODE04) ; also on sheet 38
SOC_DSSDATA20: U1.N24(DSS_DATA20/GPMC_A21/eHRPWM0_SYNCI/GPIO0_33/EMU05/BOOTMODE03) ; also on sheet 38
SOC_DSSDATA21: U1.P24(DSS_DATA21/GPMC_A22/eHRPWM_TZn0/GPIO0_32/EMU04/BOOTMODE02) ; also on sheet 38
SOC_DSSDATA22: U1.P25(DSS_DATA22/GPMC_A23/eHRPWM0_B/GPIO0_31/EMU03/BOOTMODE01) ; also on sheet 38
SOC_DSSDATA23: U1.N23(DSS_DATA23/GPMC_A24/eHRPWM0_A/GPIO0_30/EMU02/BOOTMODE00) ; also on sheet 38
SOC_DSSHSYNC: U1.P22(DSS_HSYNC/GPMC_A26/PR1_eCAP0_eCAP_SYNCIN/GPIO0_55/DSS_RFBI_HSYNC0) ; also on sheet 38
SOC_DSSPCLK: U1.N25(DSS_PCLK/GPMC_A27/PR1_eCAP0_eCAP_SYNCOUT/GPIO0_56/DSS_RFBI_REn) ; also on sheet 38
SOC_DSSVSYNC: U1.R25(DSS_VSYNC/GPMC_A25/PR1_eCAP0_eCAP_CAPIN_APWM_O/GPIO0_54/DSS_RFBI_TEVSYNC0) ; also on sheet 38
SOC_GPMC_AD0: U1.AC21(GPMC_AD0/GPIO0_00) U87.29(I/O0)
SOC_GPMC_AD1: U1.AE20(GPMC_AD1/GPIO0_01) U87.30(I/O1)
SOC_GPMC_AD2: U1.AD22(GPMC_AD2/GPIO0_02) U87.31(I/O2)
SOC_GPMC_AD3: U1.AD20(GPMC_AD3/GPIO0_03) U87.32(I/O3)
SOC_GPMC_AD4: U1.AE21(GPMC_AD4/GPIO0_04) U87.41(I/O4)
SOC_GPMC_AD5: U1.AE22(GPMC_AD5/GPIO0_05) U87.42(I/O5)
SOC_GPMC_AD6: U1.AC20(GPMC_AD6/GPIO0_06) U87.43(I/O6)
SOC_GPMC_AD7: U1.AD21(GPMC_AD7/GPIO0_07) U87.44(I/O7)
SOC_GPMC_AD8: U1.AE23(GPMC_AD8/GPIO0_08) U87.26(I/O8)
SOC_GPMC_AD9: U1.AB20(GPMC_AD9/GPIO0_09) U87.27(I/O9)
SOC_GPMC_AD10: U1.AA20(GPMC_AD10/GPIO0_10) U87.28(I/O10)
SOC_GPMC_AD11: U1.AD23(GPMC_AD11/GPIO0_11) U87.33(I/O11)
SOC_GPMC_AD12: U1.AA21(GPMC_AD12/GPIO0_12) U87.40(I/O12)
SOC_GPMC_AD13: U1.AB21(GPMC_AD13/GPIO0_13) U87.45(I/O13)
SOC_GPMC_AD14: U1.AB22(GPMC_AD14/GPIO0_14) U87.46(I/O14)
SOC_GPMC_AD15: U1.AA22(GPMC_AD15/GPIO0_15) U87.47(I/O15)
SOC_GPMC_ALE: U1.AC23(GPMC_ADVn_ALE/GPIO0_17) U87.17(ALE)
SOC_GPMC_CLE: U1.AC24(GPMC_BEn0_CLE/GPIO0_20) U87.16(CLE)
SOC_GPMC_CSN0: U1.AB25(GPMC_CSn0/GPIO0_26) U87.9(~{CE})
SOC_GPMC_RE#: U1.AC22(GPMC_OEn_REn/GPIO0_18) U87.8(~{RE})
SOC_GPMC_WAIT0: R761.2 U1.Y24(GPMC_WAIT0/GPIO0_22) U87.7(R/~{B})
SOC_GPMC_WE#: U1.Y22(GPMC_WEn/GPIO0_19) U87.18(~{WE})
SOC_GPMC_WP#: R760.2 U1.W25(GPMC_WPn/GPIO0_24) U87.19(~{WP})
SOC_I2C1_SCL: J21.3 ; also on sheet 22 23 33 35 37
SOC_I2C1_SDA: J21.4 ; also on sheet 22 23 33 35 37
SOC_MMC0_CLK: R436.2 U1.F13(PR1_PRU0_GPO15/PR1_PRU0_GPI15/MMC0_CLK/GPIO1_21)
SOC_MMC0_CLK_R: J37.5(CLK) R242.1 R436.1 U111.3(IO3)
SOC_MMC0_CMD: R432.2 U1.C13(PR1_PRU0_GPO16/PR1_PRU0_GPI16/MMC0_CMD/GPIO1_22)
SOC_MMC0_CMD_R: J37.3(CMD) R432.1 R780.1 U111.6(IO4)
SOC_MMC0_DAT0: R427.2 U1.B13(PR1_PRU0_GPO14/PR1_PRU0_GPI14/MMC0_DAT0/GPIO1_20)
SOC_MMC0_DAT0_R: J37.7(DAT0) R427.1 R779.1 U111.2(IO2)
SOC_MMC0_DAT1: R424.2 U1.A13(PR1_PRU0_GPO13/PR1_PRU0_GPI13/MMC0_DAT1/GPIO1_19)
SOC_MMC0_DAT1_R: J37.8(DAT1) R424.1 R777.1 U111.1(IO1)
SOC_MMC0_DAT2: R418.2 U1.A11(PR1_PRU0_GPO12/PR1_PRU0_GPI12/MMC0_DAT2/GPIO1_18)
SOC_MMC0_DAT2_R: J37.1(DAT2) R418.1 R776.1 U111.8(IO6)
SOC_MMC0_DAT3: R421.2 U1.A12(PR1_PRU0_GPO11/PR1_PRU0_GPI11/MMC0_DAT3/GPIO1_17)
SOC_MMC0_DAT3_R: J37.2(CD/DAT3) R421.1 R778.1 U111.7(IO5)
SOC_MMC0_SDCD: J37.9(CD1) R577.1 U1.F12(PR1_PRU0_GPO6/PR1_PRU0_GPI6/MMC0_SDCD/GPIO1_12/MCASP0_AXR11) U107.3(IO1)
SOC_RESETSTATz: U58.2(B) ; also on sheet 11 17 18 22 23 25 26 31 33 45 46
TOUCH_INTn: J21.5 R729.2 ; also on sheet 12
TSC_WAKEn: U58.1(A) ; also on sheet 47
TSC_WAKEn_AND: J21.6 U58.4(Y)
VLED+: C235.1 C734.1 J22.2 TP152.1(TP) U53.9(OUT)
VLED-: J22.1 R438.1 U53.5(FB)
N14027466: R522.1 U82.N5(7A1) U82.N6(7A2) U82.P5(7A3) U82.P6(7A4) U82.R5(8A1) U82.R6(8A2) U82.T5(8A4) U82.T6(8A3)
N14027930: R517.2 U82.T3(\~{8OE}) U82.T4(\~{7OE})
N16781633: R426.1 R721.1 U53.3(SS)
N16781680: Q12.3(D) R721.2
N16781762: R725.2 U53.6(EN)
N16781794: R456.2 U53.7(FSW)
N17473267: R509.1 U82.L1(6Y2)
N19250103: R523.2 SW13.1
N20247908: R510.1 U82.L2(6Y1)
N20273568: R508.1 U82.M2(6Y3)
N20391651: R507.1 U82.M1(6Y4)
N22391170: R808.2 SW14.1

Not connected (* = marked no-connect by the designer): J22 35* 37* 38* 39* 40*; U80 1(NC)*; U82 N1(7Y2)* N2(7Y1)* P1(7Y4)* P2(7Y3)* R1(8Y2)* R2(8Y1)* T1(8Y3)* T2(8Y4)*; U87 1(NC-1)* 2(NC-2)* 3(NC-3)* 4(NC-4)* 5(NC-5)* 6(NC-6)* 10(NC-7)* 11(NC-8)* 14(NC-9)* 15(NC-10)* 20(NC-11)* 21(NC-12)* 22(NC-13)* 23(NC-14)* 24(NC-15)* 35(NC-16)* 38(DNU)*; U107 2(NC)* 5(IO2)*; U111 4(NC1)* 9(NC2)*

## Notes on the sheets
sheet 19
- NAND Flash
- MICRO SD CARD
- Note: Resistors R418,R421,R432,R436,R427, R424
  should be placed near the SoC
sheet 20
- DSS BUFFER 1
- DSS BUFFER 2
- HDMI
- HDMI
- LCD
- LCD
- SELECTION LCD AND HDMI
- HDMI/LCD  SWITCH SELECTION
- SW14
- SW13
- DEVICE
- ON
- ON
- HDMI ON
- OFF
- OFF
- LCD ON
- OFF
- ON
- NOT VALID
- ON
- OFF
- NOT VALID
sheet 21
- LCD CONNECTOR
- TOUCH SCREEN CONNECTOR
- I2C ADDRESS: 0x70 (WRITE), 0x71 (READ)
- SOC DSS
- BACKLIGHT POWER
- ECAP0_IN_PWM0_OUT
